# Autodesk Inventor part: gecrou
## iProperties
Shininess: 70.0
Length Units: 11269
Angle Units: 11279
Time Units: 11290
Mass Units: 11283
Length Display Precision: 3
Angle Display Precision: 2
Created: 2001-12
Part Number: gecrou
Material: Par défaut
Document SubType Name: Modélisation
Designer: pichon
Density: 0.0
Volumn: 0.0
Area: 0.0
PropertySet Name: Model Information
Control State: 0
Master: False
Checked Out: False
Author: pichon
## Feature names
1. Extrusion1
2. Révolution1 [Revolution]
